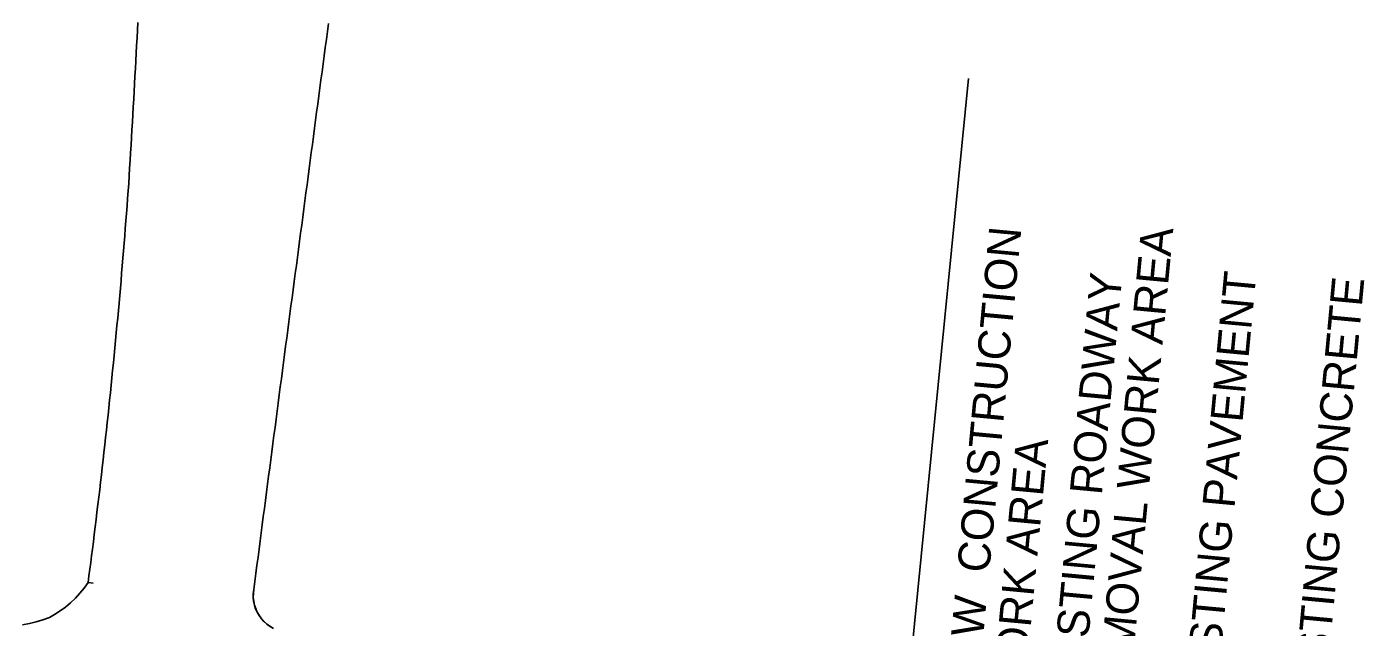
# Model space of a CAD drawing. Extents: x 1795987 to 1799700, y 243690 to 251545.
# Drawn here: x 1797633.6 to 1797957.6, y 245754 to 245899.5 of the extents above; entities that cross this region are included whole.
import ezdxf

# ---------------------------------------------------------------- set-up
doc = ezdxf.new("R2010")
doc.units = 0
doc.layers.add('LEGEND', color=7, linetype='Continuous')
doc.layers.add('Level 62', color=7, linetype='Continuous')

msp = doc.modelspace()

# ---------------------------------------------------------------- linework, layer by layer
at = {"layer": 'LEGEND'}
msp.add_line((1797817.74, 245443.45), (1797861.68, 245886.96), dxfattribs=at)
at = {"layer": 'Level 62'}
for p, q in [((1797660.4, 245898.67), (1797660.3, 245896.82)), ((1797660.5, 245900.53), (1797660.4, 245898.67)), ((1797706.15, 245896.39), (1797706.41, 245898.35)), ((1797706.41, 245898.35), (1797706.67, 245900.31)), ((1797660.2, 245894.96), (1797660.1, 245893.11)), ((1797660.3, 245896.82), (1797660.2, 245894.96)), ((1797705.88, 245894.44), (1797706.15, 245896.39)), ((1797659.99, 245891.25), (1797659.89, 245889.39)), ((1797660.1, 245893.11), (1797659.99, 245891.25)), ((1797705.36, 245890.53), (1797705.62, 245892.48)), ((1797705.62, 245892.48), (1797705.88, 245894.44)), ((1797659.89, 245889.39), (1797659.79, 245887.54)), ((1797704.84, 245886.62), (1797705.1, 245888.57)), ((1797705.1, 245888.57), (1797705.36, 245890.53)), ((1797659.68, 245885.68), (1797659.58, 245883.83)), ((1797659.79, 245887.54), (1797659.68, 245885.68)), ((1797704.58, 245884.66), (1797704.84, 245886.62)), ((1797659.48, 245881.97), (1797659.37, 245880.12)), ((1797659.58, 245883.83), (1797659.48, 245881.97)), ((1797704.06, 245880.75), (1797704.32, 245882.71)), ((1797704.32, 245882.71), (1797704.58, 245884.66)), ((1797659.27, 245878.26), (1797659.16, 245876.4)), ((1797659.37, 245880.12), (1797659.27, 245878.26)), ((1797703.54, 245876.84), (1797703.8, 245878.8)), ((1797703.8, 245878.8), (1797704.06, 245880.75)), ((1797659.16, 245876.4), (1797659.05, 245874.54)), ((1797703.28, 245874.88), (1797703.54, 245876.84)), ((1797658.94, 245872.68), (1797658.83, 245870.82)), ((1797659.05, 245874.54), (1797658.94, 245872.68)), ((1797702.76, 245870.97), (1797703.02, 245872.93)), ((1797703.02, 245872.93), (1797703.28, 245874.88)), ((1797658.71, 245868.96), (1797658.6, 245867.1)), ((1797658.83, 245870.82), (1797658.71, 245868.96)), ((1797702.25, 245867.06), (1797702.5, 245869.02)), ((1797702.5, 245869.02), (1797702.76, 245870.97)), ((1797658.6, 245867.1), (1797658.49, 245865.24)), ((1797701.99, 245865.11), (1797702.25, 245867.06)), ((1797658.38, 245863.38), (1797658.27, 245861.52)), ((1797658.49, 245865.24), (1797658.38, 245863.38)), ((1797701.47, 245861.19), (1797701.73, 245863.15)), ((1797701.73, 245863.15), (1797701.99, 245865.11)), ((1797658.13, 245859.7), (1797657.99, 245857.89)), ((1797658.27, 245861.52), (1797658.13, 245859.7)), ((1797700.95, 245857.28), (1797701.21, 245859.24)), ((1797701.21, 245859.24), (1797701.47, 245861.19)), ((1797657.86, 245856.08), (1797657.72, 245854.26)), ((1797657.99, 245857.89), (1797657.86, 245856.08)), ((1797700.69, 245855.33), (1797700.95, 245857.28)), ((1797657.58, 245852.45), (1797657.45, 245850.64)), ((1797657.72, 245854.26), (1797657.58, 245852.45)), ((1797700.17, 245851.42), (1797700.43, 245853.37)), ((1797700.43, 245853.37), (1797700.69, 245855.33)), ((1797657.45, 245850.64), (1797657.31, 245848.83)), ((1797699.65, 245847.51), (1797699.91, 245849.46)), ((1797699.91, 245849.46), (1797700.17, 245851.42)), ((1797657.16, 245847.02), (1797657.01, 245845.2)), ((1797657.31, 245848.83), (1797657.16, 245847.02)), ((1797699.4, 245845.55), (1797699.65, 245847.51)), ((1797656.86, 245843.39), (1797656.71, 245841.58)), ((1797657.01, 245845.2), (1797656.86, 245843.39)), ((1797698.88, 245841.64), (1797699.14, 245843.59)), ((1797699.14, 245843.59), (1797699.4, 245845.55)), ((1797656.56, 245839.77), (1797656.41, 245837.95)), ((1797656.71, 245841.58), (1797656.56, 245839.77)), ((1797698.36, 245837.73), (1797698.62, 245839.68)), ((1797698.62, 245839.68), (1797698.88, 245841.64)), ((1797656.26, 245836.14), (1797656.09, 245834.33)), ((1797656.41, 245837.95), (1797656.26, 245836.14)), ((1797698.1, 245835.77), (1797698.36, 245837.73)), ((1797656.09, 245834.33), (1797655.93, 245832.52)), ((1797697.58, 245831.86), (1797697.84, 245833.82)), ((1797697.84, 245833.82), (1797698.1, 245835.77)), ((1797655.76, 245830.71), (1797655.6, 245828.9)), ((1797655.93, 245832.52), (1797655.76, 245830.71)), ((1797697.06, 245827.95), (1797697.32, 245829.9)), ((1797697.32, 245829.9), (1797697.58, 245831.86)), ((1797655.43, 245827.09), (1797655.26, 245825.28)), ((1797655.6, 245828.9), (1797655.43, 245827.09)), ((1797696.8, 245825.99), (1797697.06, 245827.95)), ((1797655.1, 245823.47), (1797654.92, 245821.66)), ((1797655.26, 245825.28), (1797655.1, 245823.47)), ((1797696.29, 245822.07), (1797696.55, 245824.04)), ((1797696.55, 245824.04), (1797696.8, 245825.99)), ((1797654.92, 245821.66), (1797654.74, 245819.85)), ((1797695.77, 245818.14), (1797696.03, 245820.1)), ((1797696.03, 245820.1), (1797696.29, 245822.07)), ((1797654.56, 245818.04), (1797654.38, 245816.23)), ((1797654.74, 245819.85), (1797654.56, 245818.04)), ((1797695.52, 245816.17), (1797695.77, 245818.14)), ((1797654.2, 245814.42), (1797654.02, 245812.61)), ((1797654.38, 245816.23), (1797654.2, 245814.42)), ((1797695, 245812.24), (1797695.26, 245814.21)), ((1797695.26, 245814.21), (1797695.52, 245816.17)), ((1797653.84, 245810.8), (1797653.65, 245808.99)), ((1797654.02, 245812.61), (1797653.84, 245810.8)), ((1797694.49, 245808.31), (1797694.74, 245810.27)), ((1797694.74, 245810.27), (1797695, 245812.24)), ((1797653.46, 245807.18), (1797653.26, 245805.37)), ((1797653.65, 245808.99), (1797653.46, 245807.18)), ((1797694.23, 245806.34), (1797694.49, 245808.31)), ((1797653.26, 245805.37), (1797653.07, 245803.57)), ((1797693.71, 245802.41), (1797693.97, 245804.38)), ((1797693.97, 245804.38), (1797694.23, 245806.34)), ((1797652.88, 245801.76), (1797652.68, 245799.95)), ((1797653.07, 245803.57), (1797652.88, 245801.76)), ((1797693.46, 245800.44), (1797693.71, 245802.41)), ((1797652.49, 245798.14), (1797652.28, 245796.34)), ((1797652.68, 245799.95), (1797652.49, 245798.14)), ((1797692.94, 245796.51), (1797693.2, 245798.48)), ((1797693.2, 245798.48), (1797693.46, 245800.44)), ((1797652.08, 245794.53), (1797651.87, 245792.72)), ((1797652.28, 245796.34), (1797652.08, 245794.53)), ((1797692.43, 245792.58), (1797692.69, 245794.55)), ((1797692.69, 245794.55), (1797692.94, 245796.51)), ((1797651.66, 245790.92), (1797651.45, 245789.11)), ((1797651.87, 245792.72), (1797651.66, 245790.92)), ((1797692.17, 245790.61), (1797692.43, 245792.58)), ((1797651.45, 245789.11), (1797651.24, 245787.3)), ((1797691.66, 245786.68), (1797691.91, 245788.65)), ((1797691.91, 245788.65), (1797692.17, 245790.61)), ((1797651.04, 245785.5), (1797650.82, 245783.69)), ((1797651.24, 245787.3), (1797651.04, 245785.5)), ((1797691.14, 245782.75), (1797691.4, 245784.71)), ((1797691.4, 245784.71), (1797691.66, 245786.68)), ((1797650.59, 245781.89), (1797650.37, 245780.08)), ((1797650.82, 245783.69), (1797650.59, 245781.89)), ((1797690.88, 245780.78), (1797691.14, 245782.75)), ((1797650.15, 245778.28), (1797649.93, 245776.47)), ((1797650.37, 245780.08), (1797650.15, 245778.28)), ((1797690.37, 245776.85), (1797690.63, 245778.82)), ((1797690.63, 245778.82), (1797690.88, 245780.78)), ((1797649.71, 245774.67), (1797649.48, 245772.86)), ((1797649.93, 245776.47), (1797649.71, 245774.67)), ((1797689.85, 245772.92), (1797690.11, 245774.88)), ((1797690.11, 245774.88), (1797690.37, 245776.85)), ((1797649.48, 245772.86), (1797649.27, 245771.25)), ((1797689.6, 245770.95), (1797689.85, 245772.92)), ((1797649.07, 245769.63), (1797648.86, 245768.02)), ((1797649.27, 245771.25), (1797649.07, 245769.63)), ((1797689.08, 245767.02), (1797689.34, 245768.99)), ((1797689.34, 245768.99), (1797689.6, 245770.95)), ((1797648.65, 245766.41), (1797648.44, 245764.79)), ((1797648.86, 245768.02), (1797648.65, 245766.41)), ((1797688.57, 245763.09), (1797688.83, 245765.05)), ((1797688.83, 245765.05), (1797689.08, 245767.02)), ((1797646.47, 245762.22), (1797645.36, 245761.04)), ((1797647.49, 245763.48), (1797646.47, 245762.22)), ((1797648.44, 245764.79), (1797647.49, 245763.48)), ((1797688.45, 245761.22), (1797688.57, 245763.09)), ((1797642.95, 245758.88), (1797641.65, 245757.92)), ((1797644.19, 245759.92), (1797642.95, 245758.88)), ((1797645.36, 245761.04), (1797644.19, 245759.92)), ((1797688.73, 245759.36), (1797688.45, 245761.22)), ((1797689.39, 245757.61), (1797688.73, 245759.36)), ((1797635.88, 245755.26), (1797634.24, 245754.86)), ((1797637.5, 245755.76), (1797635.88, 245755.26)), ((1797639.09, 245756.35), (1797637.5, 245755.76)), ((1797640.29, 245757.03), (1797639.09, 245756.35)), ((1797641.65, 245757.92), (1797640.29, 245757.03)), ((1797690.41, 245756.04), (1797689.39, 245757.61)), ((1797691.74, 245754.71), (1797690.41, 245756.04)), ((1797634.24, 245754.86), (1797632.58, 245754.56)), ((1797693.32, 245753.7), (1797691.74, 245754.71))]:
    msp.add_line(p, q, dxfattribs=at)
for points in [[(1797660.5, 245900.53), (1797660.4, 245898.67), (1797660.3, 245896.82), (1797660.2, 245894.96), (1797660.1, 245893.11), (1797659.99, 245891.25), (1797659.89, 245889.39), (1797659.79, 245887.54), (1797659.68, 245885.68), (1797659.58, 245883.83), (1797659.48, 245881.97), (1797659.37, 245880.12), (1797659.27, 245878.26), (1797659.16, 245876.4), (1797659.05, 245874.54), (1797658.94, 245872.68), (1797658.83, 245870.82), (1797658.71, 245868.96), (1797658.6, 245867.1), (1797658.49, 245865.24), (1797658.38, 245863.38), (1797658.27, 245861.52), (1797658.13, 245859.7), (1797657.99, 245857.89), (1797657.86, 245856.08), (1797657.72, 245854.26), (1797657.58, 245852.45), (1797657.45, 245850.64), (1797657.31, 245848.83), (1797657.16, 245847.02), (1797657.01, 245845.2), (1797656.86, 245843.39), (1797656.71, 245841.58), (1797656.56, 245839.77), (1797656.41, 245837.95), (1797656.26, 245836.14), (1797656.09, 245834.33), (1797655.93, 245832.52), (1797655.76, 245830.71), (1797655.6, 245828.9), (1797655.43, 245827.09), (1797655.26, 245825.28), (1797655.1, 245823.47), (1797654.92, 245821.66), (1797654.74, 245819.85), (1797654.56, 245818.04), (1797654.38, 245816.23), (1797654.2, 245814.42), (1797654.02, 245812.61), (1797653.84, 245810.8), (1797653.65, 245808.99), (1797653.46, 245807.18), (1797653.26, 245805.37), (1797653.07, 245803.57), (1797652.88, 245801.76), (1797652.68, 245799.95), (1797652.49, 245798.14), (1797652.28, 245796.34), (1797652.08, 245794.53), (1797651.87, 245792.72), (1797651.66, 245790.92), (1797651.45, 245789.11), (1797651.24, 245787.3), (1797651.04, 245785.5), (1797650.82, 245783.69), (1797650.59, 245781.89), (1797650.37, 245780.08), (1797650.15, 245778.28), (1797649.93, 245776.47), (1797649.71, 245774.67), (1797649.48, 245772.86), (1797649.27, 245771.25), (1797649.07, 245769.63), (1797648.86, 245768.02), (1797648.65, 245766.41), (1797648.44, 245764.79)], [(1797706.67, 245900.31), (1797706.41, 245898.35), (1797706.15, 245896.39), (1797705.88, 245894.44), (1797705.62, 245892.48), (1797705.36, 245890.53), (1797705.1, 245888.57), (1797704.84, 245886.62), (1797704.58, 245884.66), (1797704.32, 245882.71), (1797704.06, 245880.75), (1797703.8, 245878.8), (1797703.54, 245876.84), (1797703.28, 245874.88), (1797703.02, 245872.93), (1797702.76, 245870.97), (1797702.5, 245869.02), (1797702.25, 245867.06), (1797701.99, 245865.11), (1797701.73, 245863.15), (1797701.47, 245861.19), (1797701.21, 245859.24), (1797700.95, 245857.28), (1797700.69, 245855.33), (1797700.43, 245853.37), (1797700.17, 245851.42), (1797699.91, 245849.46), (1797699.65, 245847.51), (1797699.4, 245845.55), (1797699.14, 245843.59), (1797698.88, 245841.64), (1797698.62, 245839.68), (1797698.36, 245837.73), (1797698.1, 245835.77), (1797697.84, 245833.82), (1797697.58, 245831.86), (1797697.32, 245829.9), (1797697.06, 245827.95), (1797696.8, 245825.99), (1797696.55, 245824.04), (1797696.29, 245822.07), (1797696.03, 245820.1), (1797695.77, 245818.14), (1797695.52, 245816.17), (1797695.26, 245814.21), (1797695, 245812.24), (1797694.74, 245810.27), (1797694.49, 245808.31), (1797694.23, 245806.34), (1797693.97, 245804.38), (1797693.71, 245802.41), (1797693.46, 245800.44), (1797693.2, 245798.48), (1797692.94, 245796.51), (1797692.69, 245794.55), (1797692.43, 245792.58), (1797692.17, 245790.61), (1797691.91, 245788.65), (1797691.66, 245786.68), (1797691.4, 245784.71), (1797691.14, 245782.75), (1797690.88, 245780.78), (1797690.63, 245778.82), (1797690.37, 245776.85), (1797690.11, 245774.88), (1797689.85, 245772.92), (1797689.6, 245770.95), (1797689.34, 245768.99), (1797689.08, 245767.02), (1797688.83, 245765.05), (1797688.57, 245763.09)], [(1797632.58, 245754.56), (1797634.24, 245754.86), (1797635.88, 245755.26), (1797637.5, 245755.76), (1797639.09, 245756.35), (1797640.29, 245757.03), (1797641.65, 245757.92), (1797642.95, 245758.88), (1797644.19, 245759.92), (1797645.36, 245761.04), (1797646.47, 245762.22), (1797647.49, 245763.48), (1797648.44, 245764.79), (1797649.68, 245764.63)], [(1797688.57, 245763.09), (1797688.46, 245762.16), (1797688.45, 245761.22), (1797688.54, 245760.28), (1797688.73, 245759.36), (1797689.01, 245758.47), (1797689.39, 245757.61), (1797689.86, 245756.8), (1797690.41, 245756.04), (1797691.04, 245755.34), (1797691.74, 245754.71), (1797692.5, 245754.17), (1797693.32, 245753.7)]]:
    msp.add_lwpolyline(points, dxfattribs=at)

# ---------------------------------------------------------------- texts
at = {"layer": 'LEGEND'}
for s, height, p in [('NEW  CONSTRUCTION', 7.7999, (1797863.89, 245736.99)), ('REMOVAL WORK AREA', 7.7999, (1797900.36, 245733.44)), ('EXISTING ROADWAY', 7.7999, (1797889.17, 245734.48)), ('EXISTING PAVEMENT', 7.7999, (1797921.3, 245731.32)), ('EXISTING CONCRETE', 7.7999, (1797947.35, 245728.82)), ('WORK AREA', 7.8, (1797875.08, 245735.94))]:
    msp.add_text(s, height=height, rotation=84.6544, dxfattribs=at).set_placement(p)

doc.saveas('drawing.dxf')
